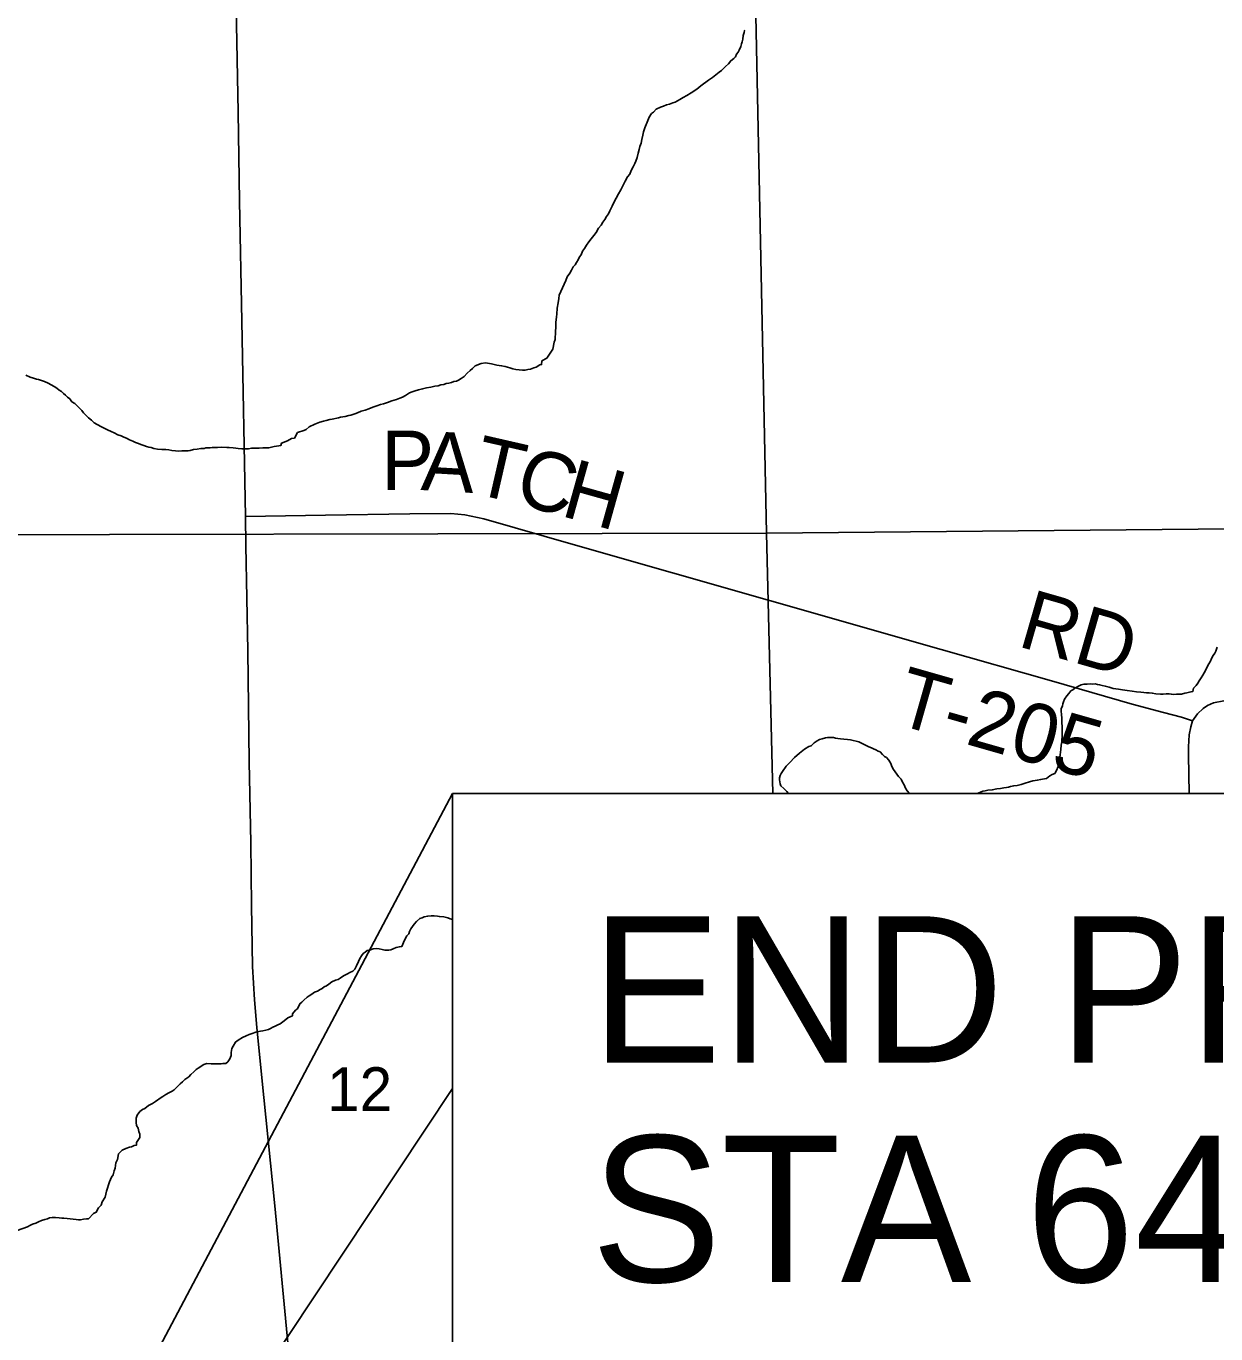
# Model space of a CAD drawing. Extents: x 10.6 to 44.6, y -2.6 to 23.4.
# Drawn here: x 17.431 to 18.57, y 19.074 to 20.326 of the extents above; entities that cross this region are included whole.
import ezdxf

# ---------------------------------------------------------------- set-up
doc = ezdxf.new("R2010")
doc.units = 0
for name, color, linetype in [('GM_X_County_Road', 7, 'Continuous'), ('GM_X_Minor_River', 7, 'Continuous'), ('GM_X_Section', 7, 'Continuous'), ('GM_X_Section_Text', 7, 'Continuous'), ('GM_X_State_Route', 7, 'Continuous'), ('GM_X_Township_Road', 7, 'Continuous'), ('GM_X_Township_Road_Text', 7, 'Continuous'), ('SH_Border', 7, 'Continuous'), ('SH_Text', 7, 'Continuous')]:
    doc.layers.add(name, color=color, linetype=linetype)

msp = doc.modelspace()

# ---------------------------------------------------------------- linework, layer by layer
at = {"layer": 'GM_X_County_Road'}
for points in [[(18.5472, 19.661), (18.552, 19.6675), (18.5574, 19.6727), (18.5616, 19.6756), (18.5673, 19.6782), (18.5772, 19.68), (18.5926, 19.6811), (18.6194, 19.6811), (18.6535, 19.6817)], [(18.544, 19.5913), (18.5434, 19.628), (18.5433, 19.6361), (18.5441, 19.6475), (18.5455, 19.6551), (18.5472, 19.661)]]:
    msp.add_lwpolyline(points, dxfattribs=at)
at = {"layer": 'GM_X_Minor_River'}
for points in [[(17.941, 20.0685), (17.9472, 20.0823), (17.9487, 20.0858), (17.9512, 20.0896), (17.9527, 20.0923), (17.9545, 20.0954), (17.9564, 20.0973), (17.9575, 20.0996), (17.959, 20.1023), (17.9604, 20.105), (17.9619, 20.1069), (17.9634, 20.1104), (17.9652, 20.1131), (17.967, 20.1162), (17.9693, 20.1193), (17.9715, 20.1224), (17.9741, 20.1254), (17.9763, 20.1285), (17.9785, 20.1324), (17.9811, 20.1355), (17.9829, 20.1382), (17.9848, 20.1409), (17.9862, 20.1436), (17.9881, 20.1463), (17.9895, 20.149), (17.9917, 20.1536), (17.9932, 20.157), (17.9954, 20.1613), (17.9976, 20.1655), (18.0001, 20.1693), (18.002, 20.1732), (18.0042, 20.1774), (18.0063, 20.1816), (18.0086, 20.1843), (18.01, 20.1878), (18.0118, 20.1913), (18.0133, 20.1943), (18.0144, 20.1966), (18.0155, 20.2001), (18.0165, 20.2043), (18.0176, 20.2077), (18.0183, 20.2108), (18.0194, 20.2138), (18.02, 20.2173), (18.0211, 20.2215), (18.0218, 20.2249), (18.0228, 20.2287), (18.0257, 20.2356), (18.0272, 20.2387), (18.0294, 20.2422), (18.0313, 20.2437), (18.0339, 20.2465), (18.038, 20.2484), (18.0407, 20.2493), (18.0437, 20.2505), (18.0467, 20.2513), (18.0497, 20.2525), (18.052, 20.2533), (18.0543, 20.2545), (18.0565, 20.2557), (18.0595, 20.2576), (18.0633, 20.2596), (18.0674, 20.262), (18.0727, 20.2655), (18.0764, 20.2687), (18.0839, 20.2741), (18.0876, 20.2769), (18.094, 20.282), (18.0962, 20.2835), (18.0981, 20.2855), (18.1003, 20.2874), (18.103, 20.2898), (18.1052, 20.2928), (18.1082, 20.2948), (18.1096, 20.2967), (18.1107, 20.299), (18.1122, 20.301), (18.1133, 20.3029), (18.1148, 20.3064), (18.1155, 20.309), (18.1162, 20.3109), (18.1169, 20.3136), (18.1172, 20.317), (18.1179, 20.3197), (18.1183, 20.3216), (18.1186, 20.322)], [(17.6463, 19.9219), (17.6501, 19.9219), (17.6539, 19.922), (17.6573, 19.9221), (17.6608, 19.9222), (17.663, 19.9222), (17.6683, 19.9235), (17.6725, 19.924), (17.6744, 19.9244), (17.6751, 19.9267), (17.6808, 19.9291), (17.6849, 19.9311), (17.6876, 19.9315), (17.6905, 19.9369), (17.6965, 19.9389), (17.6988, 19.9397), (17.7018, 19.9425), (17.7071, 19.9448), (17.712, 19.9469), (17.7154, 19.9477), (17.718, 19.9485), (17.7214, 19.9493), (17.7237, 19.9498), (17.7298, 19.951), (17.7316, 19.9515), (17.7339, 19.9519), (17.7362, 19.9523), (17.7396, 19.9532), (17.7415, 19.9536), (17.7434, 19.954), (17.7453, 19.9548), (17.7479, 19.9556), (17.7513, 19.9572), (17.7551, 19.9584), (17.7589, 19.9597), (17.7626, 19.9613), (17.7664, 19.9625), (17.7698, 19.9637), (17.7728, 19.9645), (17.7766, 19.9657), (17.7808, 19.9673), (17.7853, 19.9686), (17.7883, 19.9698), (17.791, 19.9706), (17.794, 19.9722), (17.7977, 19.9749), (17.8004, 19.9758), (17.803, 19.9769), (17.8064, 19.9778), (17.8102, 19.9786), (17.814, 19.9798), (17.8181, 19.9803), (17.8219, 19.9812), (17.825, 19.9816), (17.8276, 19.9824), (17.8306, 19.9829), (17.8329, 19.9837), (17.8352, 19.9841), (17.8378, 19.9849), (17.8401, 19.9857), (17.8427, 19.9862), (17.8446, 19.987), (17.8473, 19.9885), (17.8499, 19.9905), (17.8529, 19.9936), (17.8558, 19.9963), (17.8581, 19.9983), (17.8607, 20.0006), (17.8664, 20.003), (17.8705, 20.0035), (17.8763, 20.0025), (17.8812, 20.0014), (17.8858, 20.0008), (17.8892, 20.0001), (17.8915, 19.9994), (17.8938, 19.9987), (17.8965, 19.998), (17.8996, 19.9973), (17.9026, 19.997), (17.9057, 19.9967), (17.9083, 19.9967), (17.911, 19.9972), (17.9136, 19.9976), (17.9167, 19.9988), (17.9189, 19.9996), (17.9223, 20.0016), (17.9242, 20.002), (17.9245, 20.0054), (17.929, 20.0082), (17.9349, 20.0167), (17.9363, 20.0235), (17.937, 20.0258), (17.9376, 20.0335), (17.9379, 20.0376), (17.9378, 20.0422), (17.9384, 20.0475), (17.9388, 20.0502), (17.939, 20.0559), (17.9401, 20.0612), (17.9407, 20.0651), (17.941, 20.0685)], [(17.4306, 19.9917), (17.4345, 19.9899), (17.4379, 19.9888), (17.4406, 19.9881), (17.4425, 19.9878), (17.4444, 19.987), (17.4483, 19.9856), (17.4517, 19.9841), (17.4548, 19.9827), (17.4575, 19.9809), (17.4602, 19.9794), (17.4625, 19.9775), (17.4645, 19.9761), (17.4664, 19.9742), (17.4683, 19.9727), (17.4703, 19.9709), (17.4726, 19.969), (17.4746, 19.9664), (17.4773, 19.9646), (17.4839, 19.9579), (17.4858, 19.9556), (17.4878, 19.9534), (17.4905, 19.9508), (17.4932, 19.9486), (17.4959, 19.9463), (17.4986, 19.9445), (17.5028, 19.9423), (17.5086, 19.9394), (17.5121, 19.938), (17.5151, 19.9365), (17.5186, 19.9347), (17.5217, 19.9336), (17.5243, 19.9325), (17.5267, 19.9314), (17.5297, 19.93), (17.5328, 19.9285), (17.5355, 19.9274), (17.5382, 19.9264), (17.5405, 19.9253), (17.5435, 19.9246), (17.5458, 19.9235), (17.5481, 19.9228), (17.5504, 19.9224), (17.5531, 19.9217), (17.5565, 19.9211), (17.5607, 19.9208), (17.5645, 19.9205), (17.5672, 19.9202), (17.5703, 19.9198), (17.5737, 19.9195), (17.5767, 19.9192), (17.5798, 19.9193), (17.5821, 19.9193), (17.584, 19.9194), (17.5859, 19.9194), (17.5878, 19.9198), (17.5908, 19.9207), (17.5946, 19.9211), (17.598, 19.9216), (17.601, 19.9216), (17.6029, 19.9221), (17.6048, 19.9221), (17.6067, 19.9221), (17.609, 19.9226), (17.6117, 19.9226), (17.6139, 19.9227), (17.6174, 19.9228), (17.6227, 19.9225), (17.625, 19.9225), (17.6288, 19.9222), (17.6315, 19.9219), (17.6338, 19.9216), (17.6372, 19.9213), (17.6398, 19.9213), (17.6417, 19.9214), (17.6436, 19.9214), (17.6463, 19.9219)], [(18.4199, 19.6236), (18.4206, 19.6282), (18.4212, 19.6335), (18.4215, 19.6377), (18.4222, 19.6407), (18.4222, 19.643), (18.4225, 19.6453), (18.4224, 19.6499), (18.4224, 19.6525), (18.4223, 19.6552), (18.4222, 19.6594), (18.4221, 19.6635), (18.4217, 19.667), (18.4216, 19.67), (18.4216, 19.6723), (18.4226, 19.6753), (18.423, 19.6772), (18.4237, 19.6792), (18.4248, 19.6815), (18.427, 19.6849), (18.4288, 19.6872), (18.4307, 19.6896), (18.4326, 19.6907), (18.4344, 19.6923), (18.4386, 19.6943), (18.4405, 19.6955), (18.4431, 19.6959), (18.4462, 19.696), (18.4492, 19.6964), (18.4519, 19.6961), (18.4541, 19.6962), (18.4561, 19.6958), (18.4583, 19.6955), (18.4606, 19.6948), (18.4637, 19.6941), (18.4675, 19.693), (18.4714, 19.692), (18.4763, 19.6913), (18.4801, 19.6906), (18.4847, 19.69), (18.4893, 19.6893), (18.4935, 19.6886), (18.4977, 19.6884), (18.5007, 19.688), (18.503, 19.6877), (18.5057, 19.6878), (18.5087, 19.6875), (18.5122, 19.6868), (18.5164, 19.6865), (18.519, 19.6865), (18.5221, 19.6866), (18.5247, 19.6867), (18.527, 19.6863), (18.5293, 19.686), (18.532, 19.6864), (18.5346, 19.6865), (18.5365, 19.6865), (18.5399, 19.6874), (18.5418, 19.6878), (18.5456, 19.6886), (18.5475, 19.6891), (18.5482, 19.6921), (18.5508, 19.6948), (18.5523, 19.6971), (18.5537, 19.6991), (18.5556, 19.7022), (18.5571, 19.7045), (18.5585, 19.7068), (18.5629, 19.7156), (18.5644, 19.7179), (18.5655, 19.7206), (18.5669, 19.7233), (18.5684, 19.7256), (18.5695, 19.7275), (18.5709, 19.7314)], [(18.1535, 19.6106), (18.1546, 19.6125), (18.1583, 19.6175), (18.1617, 19.621), (18.1662, 19.6257), (18.171, 19.63), (18.1759, 19.6339), (18.18, 19.6363), (18.1823, 19.6371), (18.1849, 19.6398), (18.1879, 19.6417), (18.1901, 19.6429), (18.1928, 19.6437), (18.1958, 19.6446), (18.1981, 19.645), (18.2011, 19.6451), (18.2034, 19.6451), (18.2053, 19.6444), (18.2076, 19.6441), (18.2103, 19.6437), (18.2133, 19.6434), (18.2168, 19.6431), (18.2198, 19.6428), (18.2225, 19.6421), (18.2252, 19.6414), (18.2278, 19.6407), (18.2317, 19.6389), (18.2348, 19.6374), (18.2375, 19.636), (18.2398, 19.6349), (18.2417, 19.6342), (18.244, 19.6331), (18.2463, 19.632), (18.2482, 19.6313), (18.2505, 19.6287), (18.2525, 19.6268), (18.2544, 19.6257), (18.2564, 19.6231), (18.2583, 19.6201), (18.2595, 19.6171), (18.2611, 19.6144), (18.2627, 19.6122), (18.2643, 19.61), (18.2658, 19.6077), (18.2682, 19.6051), (18.2697, 19.6021), (18.2713, 19.5995), (18.2725, 19.5965), (18.2741, 19.5938), (18.2764, 19.5913)], [(18.3415, 19.5913), (18.3419, 19.5915), (18.3441, 19.5927), (18.3464, 19.5935), (18.3487, 19.5939), (18.3513, 19.5944), (18.3555, 19.5948), (18.36, 19.5957), (18.3635, 19.5961), (18.3665, 19.5966), (18.3691, 19.597), (18.371, 19.5974), (18.3729, 19.5979), (18.376, 19.5987), (18.3794, 19.5991), (18.3832, 19.6), (18.3869, 19.6012), (18.3911, 19.6024), (18.3945, 19.6033), (18.3987, 19.6041), (18.4017, 19.6046), (18.4074, 19.6058), (18.4107, 19.6082), (18.413, 19.6094), (18.4153, 19.6106), (18.4171, 19.6133), (18.4185, 19.6171), (18.4199, 19.6236)], [(18.1606, 19.5913), (18.1589, 19.5932), (18.1561, 19.5962), (18.153, 19.5988), (18.1526, 19.6007), (18.1518, 19.6045), (18.1517, 19.6064), (18.1524, 19.6087), (18.1535, 19.6106)], [(17.6945, 19.3916), (17.6967, 19.3936), (17.6997, 19.3963), (17.7016, 19.3975), (17.7042, 19.3991), (17.7068, 19.401), (17.7095, 19.4022), (17.7121, 19.4038), (17.714, 19.4046), (17.7159, 19.4061), (17.7181, 19.4073), (17.7204, 19.4089), (17.7234, 19.4109), (17.7268, 19.4125), (17.7294, 19.4133), (17.7313, 19.4145), (17.7346, 19.4168), (17.7365, 19.4176), (17.7384, 19.4188), (17.7407, 19.42), (17.7433, 19.4212), (17.7455, 19.4231), (17.747, 19.4262), (17.7488, 19.4304), (17.7503, 19.4335), (17.7517, 19.4358), (17.7532, 19.4381), (17.7551, 19.4393), (17.7573, 19.4409), (17.7604, 19.4417), (17.763, 19.4425), (17.766, 19.443), (17.7687, 19.4426), (17.7714, 19.4419), (17.7741, 19.4412), (17.7779, 19.4413), (17.7798, 19.4417), (17.782, 19.4425), (17.785, 19.4438), (17.7881, 19.4446), (17.7904, 19.445), (17.7929, 19.4508), (17.7951, 19.455), (17.7969, 19.4569), (17.7977, 19.4592), (17.7991, 19.4619), (17.8021, 19.4662), (17.8043, 19.4689), (17.8077, 19.4716), (17.8099, 19.4724), (17.8118, 19.4732), (17.8152, 19.474), (17.8183, 19.4741), (17.8213, 19.4742), (17.8244, 19.4739), (17.8263, 19.4735), (17.8305, 19.4732), (17.8343, 19.4722), (17.8366, 19.4715), (17.8388, 19.4708)], [(17.4668, 19.1849), (17.4699, 19.1846), (17.4729, 19.1843), (17.4756, 19.1839), (17.4786, 19.1836), (17.4809, 19.1833), (17.4828, 19.1833), (17.4855, 19.1838), (17.4885, 19.1842), (17.4904, 19.1843), (17.4953, 19.1893), (17.4979, 19.1905), (17.5001, 19.1947), (17.5027, 19.1971), (17.5034, 19.2005), (17.5064, 19.2048), (17.5078, 19.2105), (17.5106, 19.2197), (17.5124, 19.2239), (17.5139, 19.2262), (17.5149, 19.23), (17.516, 19.2327), (17.5167, 19.2377), (17.5181, 19.2411), (17.5192, 19.2465), (17.5225, 19.2499), (17.5263, 19.2515), (17.5297, 19.2528), (17.5316, 19.2532), (17.5342, 19.2544), (17.5365, 19.2548), (17.5364, 19.2571), (17.5397, 19.2621), (17.5397, 19.2651), (17.5385, 19.2678), (17.538, 19.2708), (17.5365, 19.2734), (17.536, 19.2765), (17.536, 19.2787), (17.5359, 19.2806), (17.537, 19.2833), (17.5396, 19.2868), (17.5422, 19.2888), (17.5445, 19.2899), (17.5478, 19.2927), (17.5516, 19.2947), (17.5546, 19.2966), (17.5599, 19.3002), (17.5617, 19.3013), (17.5644, 19.3033), (17.5674, 19.3049), (17.5704, 19.3065), (17.5723, 19.3076), (17.5752, 19.3104), (17.5782, 19.3135), (17.5805, 19.3154), (17.5827, 19.3174), (17.5846, 19.3189), (17.5864, 19.3201), (17.5883, 19.3224), (17.5913, 19.3248), (17.5935, 19.3271), (17.5954, 19.3283), (17.6007, 19.3318), (17.6037, 19.333), (17.6079, 19.3324), (17.6113, 19.3324), (17.6143, 19.3325), (17.6174, 19.3326), (17.6193, 19.333), (17.6219, 19.333), (17.6238, 19.3346), (17.6256, 19.3373), (17.6271, 19.3404), (17.627, 19.3434), (17.6277, 19.3472), (17.6288, 19.3495), (17.631, 19.3534), (17.6336, 19.3553), (17.6378, 19.3577), (17.6415, 19.3593), (17.6442, 19.3605), (17.6472, 19.3617), (17.6506, 19.3629), (17.6551, 19.3638), (17.6574, 19.3642), (17.6601, 19.3647), (17.6627, 19.3655), (17.6646, 19.3663), (17.6668, 19.3675), (17.6691, 19.3687), (17.6717, 19.3699), (17.674, 19.3707), (17.6777, 19.3738), (17.6811, 19.3765), (17.6856, 19.3785), (17.6856, 19.3804), (17.6886, 19.3839), (17.6904, 19.3851), (17.6926, 19.3901), (17.6945, 19.3916)], [(17.4222, 19.1729), (17.432, 19.1765), (17.4343, 19.1777), (17.4369, 19.1789), (17.4399, 19.1801), (17.4426, 19.1813), (17.4456, 19.1825), (17.4486, 19.1834), (17.4512, 19.1842), (17.4531, 19.185), (17.4558, 19.1854), (17.4588, 19.1855), (17.4623, 19.1852), (17.4649, 19.1849), (17.4668, 19.1849)]]:
    msp.add_lwpolyline(points, dxfattribs=at)
at = {"layer": 'GM_X_Section'}
for points in [[(19.0401, 20.9394), (19.0693, 19.8492), (18.1394, 19.8405), (18.1171, 20.9247), (18.1295, 20.9248), (18.5902, 20.929), (19.0353, 20.9393)], [(18.1171, 20.9247), (18.1394, 19.8405), (17.1955, 19.8385), (17.1705, 20.912), (17.6263, 20.922)]]:
    msp.add_lwpolyline(points, close=True, dxfattribs=at)
for points in [[(18.1454, 19.5913), (18.1394, 19.8405), (19.0693, 19.8492), (19.0768, 19.5913)], [(18.1592, 19.0263), (18.1646, 18.8031), (17.2198, 18.8008), (17.1955, 19.8385), (18.1394, 19.8405), (18.1454, 19.5913)]]:
    msp.add_lwpolyline(points, dxfattribs=at)
at = {"layer": 'GM_X_State_Route'}
msp.add_lwpolyline([(17.6854, 19.0216), (17.6687, 19.1967), (17.6561, 19.3224), (17.6515, 19.3672), (17.6492, 19.3939), (17.6475, 19.4256), (17.6464, 19.4841), (17.6457, 19.5441), (17.6443, 19.6217), (17.6428, 19.728), (17.6411, 19.8286), (17.6406, 19.8566), (17.6372, 20.0434), (17.635, 20.1583), (17.6338, 20.2435), (17.6321, 20.3274), (17.6302, 20.4369), (17.6276, 20.6144), (17.6241, 20.7993), (17.6224, 20.8858), (17.6219, 20.9197), (17.6207, 20.9933)], dxfattribs=at)
at = {"layer": 'GM_X_Township_Road'}
msp.add_lwpolyline([(18.5472, 19.661), (18.5368, 19.6643), (18.5195, 19.6688), (18.4895, 19.6769), (18.4121, 19.6991), (18.3065, 19.7291), (18.1424, 19.7762), (17.9567, 19.829), (17.8689, 19.8544), (17.8506, 19.8581), (17.8374, 19.8595), (17.7981, 19.8592), (17.7174, 19.8579), (17.6406, 19.8566)], dxfattribs=at)
at = {"layer": 'SH_Border'}
for points in [[(17.8388, 19.5913), (17.1022, 18.1998), (17.8388, 19.3088)], [(17.8388, 19.5913), (19.6562, 19.5913), (19.6562, 19.0263), (17.8388, 19.0263)]]:
    msp.add_lwpolyline(points, close=True, dxfattribs=at)

# ---------------------------------------------------------------- texts
at = {"layer": 'GM_X_Section_Text'}
msp.add_text('12', height=0.04186, rotation=0, dxfattribs=at).set_placement((17.7188, 19.2874))
at = {"layer": 'GM_X_Township_Road_Text'}
for s, height, rotation, p in [('P', 0.0568, 359.9097, (17.7705, 19.8819)), ('A', 0.0568, 356.6904, (17.808, 19.8819)), ('T', 0.0568, 347.0895, (17.8554, 19.8793)), ('C', 0.0568, 344.484, (17.8962, 19.87)), ('H', 0.0568, 344.3573, (17.9411, 19.8575)), ('RD', 0.05682, 343.9195, (18.3784, 19.7327)), ('T-205', 0.05682, 344.0546, (18.2597, 19.6588))]:
    msp.add_text(s, height=height, rotation=rotation, dxfattribs=at).set_placement(p)
at = {"layer": 'SH_Text'}
for s, p in [('END PROJECT', (17.9714, 19.3338)), ('STA 644+83.00', (17.9714, 19.1238))]:
    msp.add_text(s, height=0.14, dxfattribs=at).set_placement(p)

doc.saveas('drawing.dxf')
